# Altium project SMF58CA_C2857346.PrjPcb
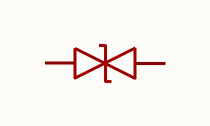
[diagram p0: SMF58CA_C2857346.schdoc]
1 sheet, 1 parts. Net scope: global (net labels, ports and power ports of the same name join across sheets).

## Sheet SMF58CA_C2857346.schdoc
size 127 x 101 mm

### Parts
D?  smf58ca_c2857346  [SOD-123FL_L2.8-W1.8-LS3.7-BI]  (value not drawn)

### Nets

Not connected (* = marked no-connect by the designer): D? 1(K) 2(A)

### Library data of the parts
D? = smf58ca_c2857346: 极性:双向;反向截止电压(Vrwm):58V;钳位电压:93.6V;峰值脉冲电流(Ipp):2.1A;峰值脉冲功率(Ppp):200W@10/1000us;击穿电压(VBR):64V;; Manufacturer: JSMSEMI(杰盛微); AddInBom: yes; ModelId: d105299b3871451c86f679efef28ff8f; ModelTransform: 145.669,70.866,0,0,0,0,0,0,0; Polarity: 双向; Reverse Stand-Off Voltage (Vrwm): 58V; Clamping Voltage: 93.6V; Peak Pulse Current (Ipp): 2.1A; Voltage - Breakdown: 64V; Reverse Leakage Current (Ir): 1uA; Number of Channels: 单路; Type: TVS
